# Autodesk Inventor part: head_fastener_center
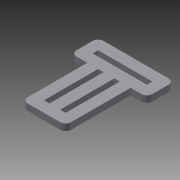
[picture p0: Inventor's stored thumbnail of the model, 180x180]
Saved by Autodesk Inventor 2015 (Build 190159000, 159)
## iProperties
Created: 2015-06
Part Number: head_fastener_center
Material: Generic
Document SubType Name: Modeling
Designer: sungeun
Density: 1 g/cm^3
Appearance: Default
Author: sungeun
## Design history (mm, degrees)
sketch "Sketch1" dims "d8" = 10
  geometry: L1 (-10, 25)-(-5, 25); L2 (-5, 25)-(-5, -25); L3 (-5, -25)-(-10, -25); L4 (-10, -25)-(-10, 25); L5 (5, 25)-(10, 25); L6 (5, -25)-(5, 25); L7 (10, 25)-(10, -25); L8 (10, -25)-(5, -25); L9 (-25, 40)-(25, 40); L10 (25, 40)-(25, 35); L11 (25, 35)-(-25, 35); L12 (-25, 35)-(-25, 40); L13 (-35, 50)-(35, 50); L14 (35, 50)-(35, 25); L15 (35, 25)-(20, 25); L16 (20, 25)-(20, -35); L17 (20, -35)-(-20, -35); L18 (-20, -35)-(-20, 25); L19 (-20, 25)-(-35, 25); L20 (-35, 25)-(-35, 50); 5 further points
  constraints: 40 end point, 8 perpendicular, 4 horizontal, 4 parallel, 2 midpoint, 1 coincident, 1 collinear, 1 horizontal alignment, 1 vertical, 1 vertical alignment, 8 other
  dimensions: "d0" = 5 distance of L2.end L3.end; "d1" = 50 distance of L3.end L1.start; "d2" = 5 distance from line of L2 point (0, 0); "d5" = 15 distance of L1.start L5.start; "d10" = 5 distance of L9.end L10.end; "d11" = 50 distance of L9.start L9.end; "d12" = 10 distance between parallel lines of L5 L11; "d13" = 10 distance between parallel lines of L16 L7; "d14" = 10 distance between parallel lines of L18 L4; "d15" = 10 distance between parallel lines of L8 L17; "d16" = 10 distance between parallel lines of L13 L9; "d17" = 10 distance between parallel lines of L14 L10; "d18" = 10 distance between parallel lines of L15 L11; "d19" = 10 distance between parallel lines of L11 L19; "d20" = 10 distance between parallel lines of L12 L20
extrude "Extrusion1" new body sketch "Sketch1" distance "d21" = 6; taper "d22" = 0 deg
fillet "Fillet1" dims "d23" = 5
body "Solid1"
